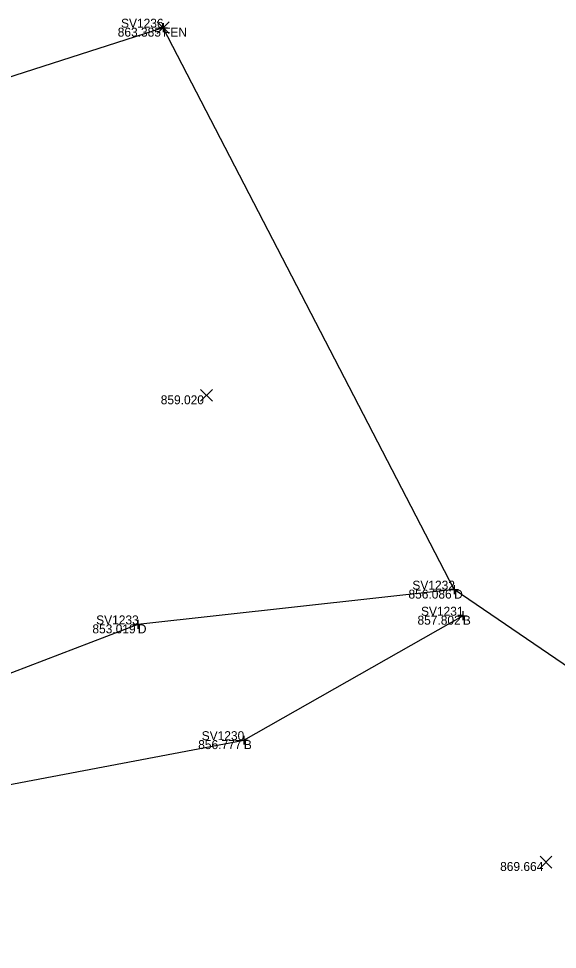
# Model space of a CAD drawing. Extents: x 2125299 to 2129212, y 713100 to 714300.
# Drawn here: x 2128355.7 to 2128416, y 714146 to 714250.2 of the extents above; entities that cross this region are included whole.
import ezdxf

# ---------------------------------------------------------------- set-up
doc = ezdxf.new("R2010")
doc.units = 0
for name, color, linetype in [('DR_X_Ditch', 7, 'Continuous'), ('DT_X_Terrain_Boundary', 7, 'Continuous'), ('RD_X_Fence', 7, 'Continuous'), ('RW_P_Esmt_TMP', 7, 'Continuous'), ('RW_X_Esmt_CH', 7, 'Continuous'), ('RW_X_Fee_WL', 7, 'Continuous'), ('SV_X_Break_Lines', 7, 'Continuous'), ('SV_X_Mon_Cells_Found', 7, 'Continuous'), ('SV_X_Text_Elevation', 7, 'Continuous')]:
    doc.layers.add(name, color=color, linetype=linetype)

msp = doc.modelspace()

# ---------------------------------------------------------------- linework, layer by layer
at = {"layer": 'DR_X_Ditch'}
msp.add_lwpolyline([(2128404.43, 714186.27), (2128369.06, 714182.38), (2128353.25, 714176.31), (2128345.76, 714173.48), (2128342.57, 714173.52), (2128335.15, 714174.47), (2128320.72, 714174.93), (2128310.69, 714174.47), (2128298.55, 714171.49), (2128292.16, 714172.44), (2128287.3, 714171.9), (2128282.28, 714171.91)], dxfattribs=at)
at = {"layer": 'DT_X_Terrain_Boundary'}
msp.add_lwpolyline([(2128442.63, 714160.2), (2128404.43, 714186.27), (2128371.88, 714249.15), (2128341.8, 714239.46), (2128307.19, 714228.08), (2128286.83, 714221.22), (2128228.86, 714201.07), (2128207.39, 714193.9), (2128150.55, 714124.18), (2128126.02, 714119.43), (2128120.14, 714107.52), (2128111.88, 714086.22), (2128106.87, 714068.79), (2128101.83, 714061.27), (2128102.4, 714047.83), (2128092.73, 714045.3), (2128083.06, 714042.76), (2128073.38, 714040.23), (2128063.71, 714037.7), (2128054.04, 714035.16), (2128044.36, 714032.63), (2128034.69, 714030.09), (2128025.02, 714027.56)], dxfattribs=at)
at = {"layer": 'RD_X_Fence'}
msp.add_lwpolyline([(2128371.88, 714249.15), (2128341.8, 714239.46), (2128307.19, 714228.08), (2128228.86, 714201.07), (2128207.39, 714193.9)], dxfattribs=at)
at = {"layer": 'SV_X_Break_Lines'}
msp.add_lwpolyline([(2128257.59, 714155.56), (2128263.49, 714153.24), (2128269.27, 714148.53), (2128290.13, 714150.8), (2128296.99, 714153.38), (2128311.86, 714153.9), (2128347.24, 714163.06), (2128380.91, 714169.43), (2128405.4, 714183.35)], dxfattribs=at)
at = {"layer": 'SV_X_Mon_Cells_Found'}
for p, q in [((2128371.38, 714249.15), (2128372.38, 714249.15)), ((2128371.88, 714249.65), (2128371.88, 714248.65)), ((2128371.88, 714249.15), (2128371.88, 714249.15)), ((2128404.43, 714186.77), (2128404.43, 714185.77)), ((2128403.93, 714186.27), (2128404.93, 714186.27)), ((2128404.43, 714186.27), (2128404.43, 714186.27)), ((2128404.9, 714183.35), (2128405.9, 714183.35)), ((2128405.4, 714183.85), (2128405.4, 714182.85)), ((2128405.4, 714183.35), (2128405.4, 714183.35)), ((2128368.56, 714182.38), (2128369.56, 714182.38)), ((2128369.06, 714182.88), (2128369.06, 714181.88)), ((2128369.06, 714182.38), (2128369.06, 714182.38)), ((2128380.91, 714169.93), (2128380.91, 714168.93)), ((2128380.41, 714169.43), (2128381.41, 714169.43)), ((2128380.91, 714169.43), (2128380.91, 714169.43))]:
    msp.add_line(p, q, dxfattribs=at)
at = {"layer": 'SV_X_Text_Elevation'}
for p, q in [((2128371.21, 714248.48), (2128372.55, 714249.82)), ((2128371.21, 714249.82), (2128372.55, 714248.48)), ((2128376.07, 714207.35), (2128377.4, 714208.68)), ((2128376.07, 714208.68), (2128377.4, 714207.35)), ((2128414.03, 714155.12), (2128415.36, 714156.46)), ((2128414.03, 714156.46), (2128415.36, 714155.12))]:
    msp.add_line(p, q, dxfattribs=at)

# ---------------------------------------------------------------- texts
at = {"layer": 'RW_P_Esmt_TMP'}
for s, p in [('FEN', (2128371.88, 714248.15)), ('D', (2128404.43, 714185.27)), ('B', (2128405.4, 714182.35)), ('D', (2128369.06, 714181.38)), ('B', (2128380.91, 714168.43))]:
    msp.add_text(s, height=1, dxfattribs=at).set_placement(p)
at = {"layer": 'RW_X_Esmt_CH'}
for s, p in [('SV1236', (2128367.18, 714249.15)), ('SV1232', (2128399.76, 714186.27)), ('SV1231', (2128400.72, 714183.35)), ('SV1233', (2128364.4, 714182.38)), ('SV1230', (2128376.2, 714169.43))]:
    msp.add_text(s, height=1, dxfattribs=at).set_placement(p)
at = {"layer": 'RW_X_Fee_WL'}
for s, p in [('863.385', (2128366.81, 714248.15)), ('863.385', (2128366.81, 714248.15)), ('859.020', (2128371.62, 714207.01)), ('856.086', (2128399.32, 714185.27)), ('857.802', (2128400.33, 714182.35)), ('853.019', (2128363.98, 714181.38)), ('856.777', (2128375.81, 714168.43)), ('869.664', (2128409.57, 714154.79))]:
    msp.add_text(s, height=1, dxfattribs=at).set_placement(p)

doc.saveas('drawing.dxf')
